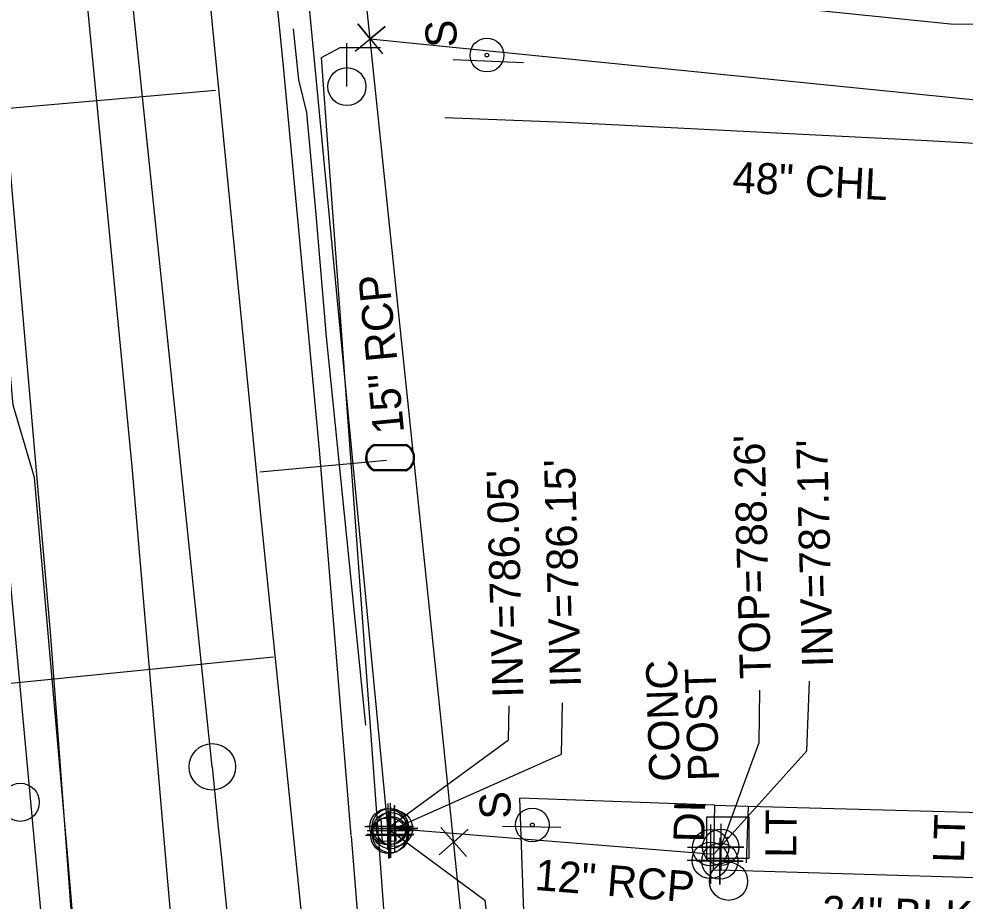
# Model space of a CAD drawing. Extents: x 1627482 to 1629573, y 760826 to 766301.
# Drawn here: x 1628290.6 to 1628412.7, y 765240 to 765353.8 of the extents above; entities that cross this region are included whole.
import ezdxf

# ---------------------------------------------------------------- set-up
doc = ezdxf.new("R2010")
doc.units = 0
for name, color, linetype in [('Exist Building', 7, 'Continuous'), ('Exist Building Text', 7, 'Continuous'), ('Exist Horizontal Alignment', 7, 'Continuous'), ('Exist Horizontal Alignment Point', 7, 'Continuous'), ('Exist Other Culture Area Outline', 7, 'Continuous'), ('Exist Other Culture Area Outline Text', 7, 'Continuous'), ('Exist Other Culture Fence Line', 7, 'Continuous'), ('Exist Other Culture Fence Line Text', 7, 'Continuous'), ('Exist Other Culture Sign CELL', 7, 'Continuous'), ('Exist Other Culture Sign Post CELL', 7, 'Continuous'), ('Exist Other Culture Sign Post Text', 7, 'Continuous'), ('Exist Other Culture Sign Text', 7, 'Continuous'), ('Exist Property Corner CELL', 7, 'Continuous'), ('Exist Property Line', 7, 'Continuous'), ('Exist Right of Way Line', 7, 'Continuous'), ('Exist Roads Change in Surface', 7, 'Continuous'), ('Exist Roads EOP', 7, 'Continuous'), ('Exist Roads EOP Other', 7, 'Continuous'), ('Exist Roads EOT', 7, 'Continuous'), ('Exist Roads Soil', 7, 'Continuous'), ('Exist Structure Minor Catch Basin Cogo Point CELL', 7, 'Continuous'), ('Exist Structure Minor Catch Basin Leader', 7, 'Continuous'), ('Exist Structure Minor Drop Inlet', 7, 'Continuous'), ('Exist Structure Minor Drop Inlet Cogo Point CELL', 7, 'Continuous'), ('Exist Structure Minor Drop Inlet Leader', 7, 'Continuous'), ('Exist Structure Minor Drop Inlet Text', 7, 'Continuous'), ('Exist Structure Minor Drop Inlet Top Elevation', 7, 'Continuous'), ('Exist Structure Minor Pipes HDPE 12 Inch Cogo Point CELL', 7, 'Continuous'), ('Exist Structure Minor Pipes HDPE 12 Inch Invert', 7, 'Continuous'), ('Exist Structure Minor Pipes HDPE 12 Inch Leader', 7, 'Continuous'), ('Exist Structure Minor Pipes RCP 12 Inch', 7, 'Continuous'), ('Exist Structure Minor Pipes RCP 12 Inch Text', 7, 'Continuous'), ('Exist Structure Minor Pipes RCP 15 Inch', 7, 'Continuous'), ('Exist Structure Minor Pipes RCP 15 Inch Cogo Point CELL', 7, 'Continuous'), ('Exist Structure Minor Pipes RCP 15 Inch Invert', 7, 'Continuous'), ('Exist Structure Minor Pipes RCP 15 Inch Leader', 7, 'Continuous'), ('Exist Structure Minor Pipes RCP 15 Inch Text', 7, 'Continuous'), ('Exist Utilities Gas UG Line SUE LOS B', 7, 'Continuous'), ('Exist Utilities Other Pole CELL', 7, 'Continuous'), ('Exist Utilities Other Pole With Base CELL', 7, 'Continuous'), ('Exist Utilities Other Pole With Base Text', 7, 'Continuous'), ('Exist Utilities Power Pole CELL', 7, 'Continuous'), ('Exist Utilities Water Meter CELL', 7, 'Continuous'), ('Exist Utilities Water UG Line SUE LOS B', 7, 'Continuous')]:
    doc.layers.add(name, color=color, linetype=linetype)

msp = doc.modelspace()

# ---------------------------------------------------------------- linework, layer by layer
at = {"layer": 'Exist Building'}
for p, q in [((1628381.03, 765243.95), (1628380.26, 765243.91)), ((1628475.95, 765241.04), (1628381.03, 765243.95))]:
    msp.add_line(p, q, dxfattribs=at)
at = {"layer": 'Exist Horizontal Alignment'}
msp.add_line((1628315.58, 765257.27), (1628296.86, 765437), dxfattribs=at)
msp.add_arc((1620544.28, 764447.73), 7813.36, 2.25819, 5.947048, dxfattribs=at)
at = {"layer": 'Exist Horizontal Alignment Point'}
msp.add_circle((1628315.58, 765257.27), 3, dxfattribs=at)
at = {"layer": 'Exist Other Culture Area Outline'}
for p, q in [((1628380.26, 765243.91), (1628380.43, 765252.35)), ((1628384.73, 765252.22), (1628384.51, 765244.88))]:
    msp.add_line(p, q, dxfattribs=at)
at = {"layer": 'Exist Other Culture Fence Line'}
msp.add_lwpolyline([(1628458.84, 765335.27), (1628431.67, 765336.73), (1628407.09, 765338.08), (1628361.22, 765340.4), (1628345.61, 765341)], dxfattribs=at)
at = {"layer": 'Exist Other Culture Sign CELL'}
for p, q in [((1628346.68, 765348.53), (1628355.77, 765348.17)), ((1628353.04, 765249.62), (1628360.59, 765249.49))]:
    msp.add_line(p, q, dxfattribs=at)
for radius in [2.18, 0.24]:
    msp.add_circle((1628356.89, 765249.78), radius, dxfattribs=at)
at = {"layer": 'Exist Other Culture Sign Post CELL'}
for radius in [2.18, 0.24]:
    msp.add_circle((1628351.03, 765349.11), radius, dxfattribs=at)
at = {"layer": 'Exist Property Corner CELL'}
for p, q in [((1628335.96, 765351.21), (1628335.96, 765351.21)), ((1628346.74, 765247.57), (1628346.74, 765247.57))]:
    msp.add_line(p, q, dxfattribs=at)
for points in [[(1628334.02, 765349.63), (1628337.89, 765352.79), (1628335.96, 765351.21), (1628334.38, 765353.15), (1628337.54, 765349.27)], [(1628344.86, 765245.93), (1628348.63, 765249.22), (1628346.74, 765247.57), (1628345.1, 765249.46), (1628348.39, 765245.69)]]:
    msp.add_lwpolyline(points, dxfattribs=at)
at = {"layer": 'Exist Property Line'}
msp.add_lwpolyline([(1628335.96, 765351.21), (1628560.64, 765328.6)], dxfattribs=at)
at = {"layer": 'Exist Right of Way Line'}
msp.add_line((1628345.42, 765260.38), (1628326.7, 765440.11), dxfattribs=at)
msp.add_arc((1620544.28, 764447.73), 7843.36, 4.169003, 5.947048, dxfattribs=at)
at = {"layer": 'Exist Roads Change in Surface'}
msp.add_lwpolyline([(1628335.42, 765262.65), (1628333.27, 765283.95), (1628330.32, 765312.74), (1628329, 765328.56), (1628327.8, 765341.7), (1628326.76, 765345.91), (1628326.08, 765352.51)], dxfattribs=at)
at = {"layer": 'Exist Roads EOP'}
for points in [[(1628275.72, 765429.87), (1628315.6, 764998.34)], [(1628455.23, 765352.81), (1628410.86, 765353.09), (1628366.98, 765357.63), (1628335.79, 765359.53)], [(1628329.68, 765348.79), (1628332.09, 765350.1), (1628334.69, 765350.1), (1628337.28, 765350.1)], [(1628354.43, 765051.34), (1628349.75, 765100.45), (1628345.26, 765150.11), (1628340.67, 765199.02), (1628329.68, 765348.79)]]:
    msp.add_lwpolyline(points, dxfattribs=at)
at = {"layer": 'Exist Roads EOP Other'}
msp.add_line((1628380.43, 765252.35), (1628384.73, 765252.22), dxfattribs=at)
at = {"layer": 'Exist Roads EOT'}
for points in [[(1628333.52, 765248.4), (1628329.4, 765298.18), (1628324.72, 765348.12), (1628319.83, 765396.83), (1628315.15, 765446.04), (1628310.38, 765495.44), (1628305.6, 765544.74), (1628300.53, 765594.55), (1628297.28, 765629.36), (1628296.07, 765643.72), (1628291.37, 765692.86), (1628286.71, 765742.17), (1628281.97, 765791.57), (1628277.28, 765840.65), (1628272.47, 765890.08), (1628267.44, 765941.93), (1628262.71, 765991.13), (1628257.98, 766041.68), (1628253.31, 766091.45), (1628248.62, 766139.51)], [(1628321.8, 765097.93), (1628317.82, 765147.67), (1628313.79, 765197.09), (1628309.5, 765246.44), (1628305.25, 765296.01), (1628300.47, 765345.4), (1628295.75, 765394.23), (1628290.92, 765443.38), (1628286.2, 765493), (1628281.48, 765542.67), (1628276.9, 765591.66), (1628272.08, 765640.85), (1628267.39, 765690.37), (1628262.64, 765739.28), (1628257.97, 765789.11), (1628253.23, 765838.22), (1628248.39, 765887.64), (1628243.39, 765938.8), (1628238.58, 765988.56), (1628233.82, 766039.14), (1628229.1, 766088.8), (1628224.69, 766136.81)], [(1628314.55, 765029.12), (1628313.14, 765048.13), (1628309.33, 765096.73), (1628305.37, 765146.19), (1628301.1, 765196.07), (1628296.94, 765245.56), (1628292.62, 765294.59), (1628289.87, 765303.96), (1628287.14, 765334.52), (1628286.34, 765344.22)], [(1628364.1, 764792.12), (1628361.32, 764852.72), (1628359.01, 764902.56), (1628356.32, 764952.1), (1628353.22, 765001.24), (1628349.59, 765050.89), (1628345.67, 765099.92), (1628341.6, 765149.64), (1628337.53, 765199.06), (1628333.54, 765248.34)]]:
    msp.add_lwpolyline(points, dxfattribs=at)
at = {"layer": 'Exist Roads Soil'}
for p, q in [((1628380.43, 765252.35), (1628355.29, 765253.22)), ((1628384.73, 765252.22), (1628414.89, 765251.4))]:
    msp.add_line(p, q, dxfattribs=at)
msp.add_lwpolyline([(1628477.41, 765226.07), (1628435.8, 765227.31), (1628388.2, 765229), (1628356.47, 765230.12), (1628355.78, 765238.63), (1628355.29, 765253.22)], dxfattribs=at)
at = {"layer": 'Exist Structure Minor Catch Basin Cogo Point CELL'}
msp.add_lwpolyline([(1628335.57, 765249.05), (1628341.57, 765249.05), (1628338.57, 765249.05), (1628338.57, 765252.05), (1628338.57, 765246.05)], dxfattribs=at)
msp.add_circle((1628338.57, 765249.05), 2.34, dxfattribs=at)
at = {"layer": 'Exist Structure Minor Catch Basin Leader'}
msp.add_lwpolyline([(1628338.57, 765249.05), (1628350.74, 765240.07), (1628351.89, 765230.35)], dxfattribs=at)
at = {"layer": 'Exist Structure Minor Drop Inlet'}
for points in [[(1628337.55, 765247.66), (1628337.37, 765250.63), (1628339.13, 765250.75), (1628339.27, 765247.68)], [(1628379.87, 765245.2), (1628379.9, 765246.85), (1628381.21, 765246.9), (1628381.1, 765245.11)]]:
    msp.add_lwpolyline(points, close=True, dxfattribs=at)
at = {"layer": 'Exist Structure Minor Drop Inlet Cogo Point CELL'}
for points in [[(1628379.9, 765249.85), (1628379.9, 765243.85), (1628379.9, 765246.85), (1628382.9, 765246.85), (1628376.9, 765246.85)], [(1628381.21, 765249.9), (1628381.21, 765243.9), (1628381.21, 765246.9), (1628384.21, 765246.9), (1628378.21, 765246.9)], [(1628379.87, 765248.2), (1628379.87, 765242.2), (1628379.87, 765245.2), (1628382.87, 765245.2), (1628376.87, 765245.2)], [(1628381.1, 765248.11), (1628381.1, 765242.11), (1628381.1, 765245.11), (1628384.1, 765245.11), (1628378.1, 765245.11)]]:
    msp.add_lwpolyline(points, dxfattribs=at)
for centre in [(1628379.9, 765246.85), (1628381.21, 765246.9), (1628379.87, 765245.2), (1628381.1, 765245.11)]:
    msp.add_circle(centre, 2.34, dxfattribs=at)
at = {"layer": 'Exist Structure Minor Drop Inlet Leader'}
msp.add_lwpolyline([(1628381.21, 765246.9), (1628386.18, 765260.43), (1628386.26, 765267.15)], dxfattribs=at)
at = {"layer": 'Exist Structure Minor Pipes HDPE 12 Inch Cogo Point CELL'}
msp.add_lwpolyline([(1628336.1, 765249.33), (1628342.1, 765249.33), (1628339.1, 765249.33), (1628339.1, 765252.33), (1628339.1, 765246.33)], dxfattribs=at)
msp.add_circle((1628339.1, 765249.33), 2.34, dxfattribs=at)
at = {"layer": 'Exist Structure Minor Pipes HDPE 12 Inch Leader'}
for points in [[(1628380.33, 765246.02), (1628392.31, 765259.32), (1628392.67, 765268.33)], [(1628339.1, 765249.33), (1628360.67, 765258.91), (1628360.78, 765265.55)]]:
    msp.add_lwpolyline(points, dxfattribs=at)
at = {"layer": 'Exist Structure Minor Pipes RCP 12 Inch'}
msp.add_line((1628339.1, 765249.33), (1628380.33, 765246.02), dxfattribs=at)
at = {"layer": 'Exist Structure Minor Pipes RCP 15 Inch'}
msp.add_line((1628338.26, 765249.55), (1628316.42, 765477.58), dxfattribs=at)
at = {"layer": 'Exist Structure Minor Pipes RCP 15 Inch Cogo Point CELL'}
for points in [[(1628338.26, 765252.55), (1628338.26, 765246.55), (1628338.26, 765249.55), (1628341.26, 765249.55), (1628335.26, 765249.55)], [(1628338.55, 765252.58), (1628338.55, 765246.58), (1628338.55, 765249.58), (1628341.55, 765249.58), (1628335.55, 765249.58)], [(1628338.37, 765251.43), (1628338.37, 765245.43), (1628338.37, 765248.43), (1628341.37, 765248.43), (1628335.37, 765248.43)], [(1628338.58, 765251.53), (1628338.58, 765245.53), (1628338.58, 765248.53), (1628341.58, 765248.53), (1628335.58, 765248.53)]]:
    msp.add_lwpolyline(points, dxfattribs=at)
for centre in [(1628338.26, 765249.55), (1628338.55, 765249.58), (1628338.37, 765248.43), (1628338.58, 765248.53)]:
    msp.add_circle(centre, 2.34, dxfattribs=at)
at = {"layer": 'Exist Structure Minor Pipes RCP 15 Inch Leader'}
msp.add_lwpolyline([(1628338.55, 765249.58), (1628353.82, 765260.78), (1628353.9, 765265.15)], dxfattribs=at)
at = {"layer": 'Exist Utilities Gas UG Line SUE LOS B'}
msp.add_lwpolyline([(1628199.46, 764849.74), (1628245.39, 764843.93), (1628286.91, 764842.44), (1628323.21, 764841.89), (1628321.41, 764890.52), (1628318.08, 764974.07), (1628312.79, 765045.73), (1628307.65, 765115.94), (1628300.97, 765190.25), (1628294.72, 765274.13), (1628289.3, 765336.67), (1628283.53, 765391.1), (1628278.4, 765447.27), (1628276.21, 765471.83)], dxfattribs=at)
at = {"layer": 'Exist Utilities Other Pole CELL'}
for centre in [(1628290.79, 765252.7), (1628382.22, 765242.51)]:
    msp.add_circle(centre, 2.46, dxfattribs=at)
at = {"layer": 'Exist Utilities Other Pole With Base CELL'}
msp.add_line((1628382.15, 765248.13), (1628382.15, 765248.13), dxfattribs=at)
msp.add_lwpolyline([(1628379.42, 765250.83), (1628384.82, 765250.83), (1628384.82, 765245.43), (1628379.42, 765245.43), (1628379.42, 765250.83)], dxfattribs=at)
msp.add_circle((1628382.15, 765248.13), 0.0707, dxfattribs=at)
at = {"layer": 'Exist Utilities Power Pole CELL'}
for q in [(1628332.96, 765350.67), (1628332.96, 765345.04)]:
    msp.add_line((1628332.96, 765345.04), q, dxfattribs=at)
msp.add_circle((1628332.96, 765345.04), 2.45, dxfattribs=at)
at = {"layer": 'Exist Utilities Water Meter CELL'}
for p, q in [((1628338.53, 765297.17), (1628338.53, 765297.17)), ((1628338.54, 765297.17), (1628338.54, 765297.17))]:
    msp.add_line(p, q, dxfattribs=at)
for points in [[(1628336.49, 765298.87), (1628340.57, 765298.87)], [(1628336.49, 765298.73), (1628340.57, 765298.73)], [(1628336.51, 765298.87), (1628340.58, 765298.87)], [(1628336.51, 765298.73), (1628340.58, 765298.73)], [(1628340.57, 765295.61), (1628336.47, 765295.61)], [(1628340.57, 765295.47), (1628336.47, 765295.47)], [(1628340.58, 765295.6), (1628336.48, 765295.6)], [(1628340.58, 765295.47), (1628336.48, 765295.47)]]:
    msp.add_lwpolyline(points, dxfattribs=at)
for centre, radius, start, end in [((1628337.22, 765297.17), 1.86, 113.178, 245.9794), ((1628337.24, 765297.16), 1.86, 113.178, 245.9794), ((1628337.24, 765297.17), 1.73, 115.3009, 243.7824), ((1628337.25, 765297.16), 1.73, 115.3009, 243.7824), ((1628339.82, 765297.17), 1.86, 293.6483, 66.3084), ((1628339.84, 765297.17), 1.73, 295.1272, 64.8728), ((1628339.84, 765297.17), 1.86, 293.6483, 66.3084), ((1628339.85, 765297.17), 1.73, 295.1272, 64.8728)]:
    msp.add_arc(centre, radius, start, end, dxfattribs=at)
at = {"layer": 'Exist Utilities Water UG Line SUE LOS B'}
for p, q in [((1628274.86, 765341), (1628315.98, 765344.58)), ((1628338.07, 765296.8), (1628321.7, 765295.29)), ((1628283.87, 765267.49), (1628323.49, 765271.48))]:
    msp.add_line(p, q, dxfattribs=at)
msp.add_lwpolyline([(1628407.24, 763655.16), (1628402.4, 763754.94), (1628399.06, 763856.51), (1628396.12, 763915.33), (1628393.3, 763992.46), (1628390.7, 764066.34), (1628386.72, 764168.39), (1628382.56, 764256.29), (1628378.23, 764373.67), (1628375.54, 764455.63), (1628372.03, 764542.25), (1628370.17, 764583.36), (1628366.9, 764671.42), (1628365.27, 764739.23), (1628362.16, 764808.05), (1628361.5, 764823.25), (1628356.13, 764896.21), (1628352.11, 764986.77), (1628341.94, 765081.92), (1628331.48, 765195.63), (1628321.82, 765290.23), (1628312.98, 765379.55), (1628303.79, 765478.36)], dxfattribs=at)

# ---------------------------------------------------------------- texts
at = {"layer": 'Exist Building Text'}
msp.add_text('24" BLK WALL', height=4, rotation=357.8286, dxfattribs=at).set_placement((1628394.21, 765236.67))
at = {"layer": 'Exist Other Culture Area Outline Text'}
for s, p in [('CONC', (1628376.01, 765255.42)), ('POST', (1628381.01, 765255.51))]:
    msp.add_text(s, height=4, rotation=91.7713, dxfattribs=at).set_placement(p)
at = {"layer": 'Exist Other Culture Fence Line Text'}
msp.add_text('48" CHL', height=4, rotation=357.101, dxfattribs=at).set_placement((1628382.67, 765331.4))
at = {"layer": 'Exist Other Culture Sign Post Text'}
msp.add_text('S', height=4, rotation=91.7713, dxfattribs=at).set_placement((1628347.16, 765350.15))
at = {"layer": 'Exist Other Culture Sign Text'}
msp.add_text('S', height=4, rotation=93.6077, dxfattribs=at).set_placement((1628354.19, 765250.66))
at = {"layer": 'Exist Structure Minor Drop Inlet Text'}
msp.add_text('DI', height=4, rotation=88.633, dxfattribs=at).set_placement((1628379.09, 765247.5))
at = {"layer": 'Exist Structure Minor Drop Inlet Top Elevation'}
msp.add_text("TOP=788.26'", height=4, rotation=91.5197, dxfattribs=at).set_placement((1628387.69, 765268.69))
at = {"layer": 'Exist Structure Minor Pipes HDPE 12 Inch Invert'}
for s, p in [("INV=787.17'", (1628395.72, 765270.18)), ("INV=786.15'", (1628363.17, 765267.62))]:
    msp.add_text(s, height=4, rotation=91.5197, dxfattribs=at).set_placement(p)
at = {"layer": 'Exist Structure Minor Pipes RCP 12 Inch Text'}
msp.add_text('12" RCP', height=4, rotation=355.419, dxfattribs=at).set_placement((1628357.11, 765241.4))
at = {"layer": 'Exist Structure Minor Pipes RCP 15 Inch Invert'}
msp.add_text("INV=786.05'", height=4, rotation=91.5197, dxfattribs=at).set_placement((1628355.75, 765266.24))
at = {"layer": 'Exist Structure Minor Pipes RCP 15 Inch Text'}
msp.add_text('15" RCP', height=4, rotation=95.4723, dxfattribs=at).set_placement((1628340.35, 765300.44))
at = {"layer": 'Exist Utilities Other Pole With Base Text'}
for rotation, p in [(89.3435, (1628390.95, 765245.52)), (88.348, (1628412.6, 765244.84))]:
    msp.add_text('LT', height=4, rotation=rotation, dxfattribs=at).set_placement(p)

doc.saveas('drawing.dxf')
